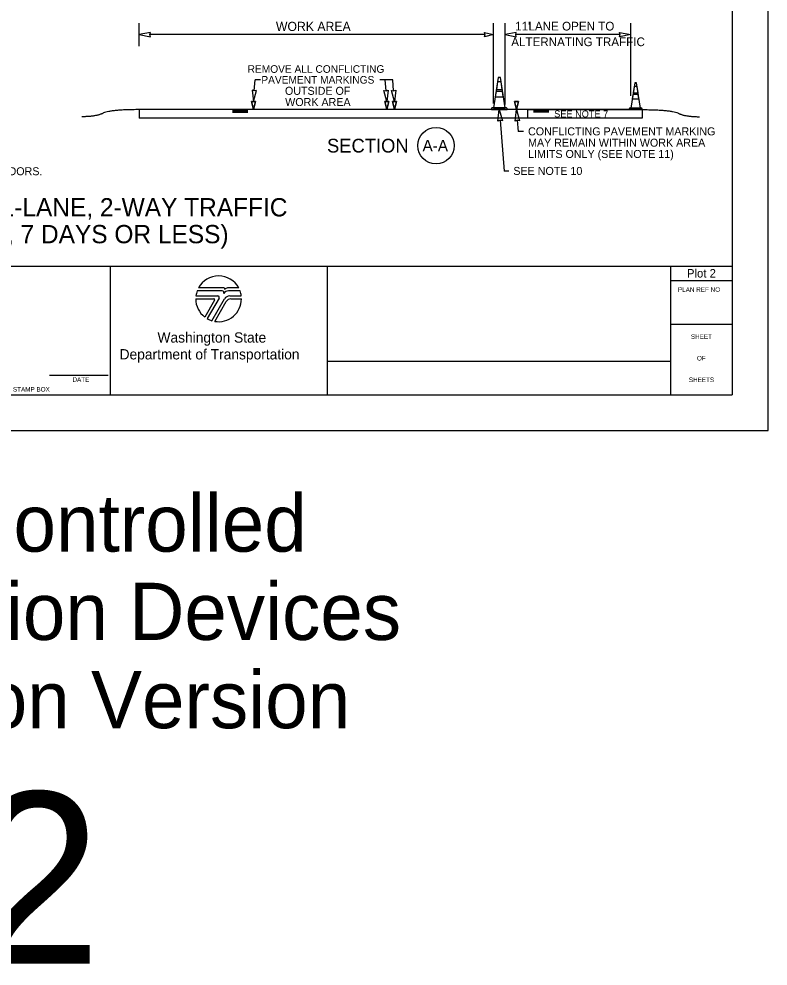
# Model space of a CAD drawing. Extents: x 99979.8 to 100075.7, y 99995 to 100010.7.
# Drawn here: x 100029.51 to 100036.06, y 99995.01 to 100003.29 of the extents above; entities that cross this region are included whole.
import ezdxf

# ---------------------------------------------------------------- set-up
doc = ezdxf.new("R2010")
doc.units = 0
for name, color, linetype in [('SH_DE_DetailHeading1Text', 7, 'Continuous'), ('SH_GI_GeneralNotesBodyText', 7, 'Continuous'), ('SH_GI_PlotLimits', 7, 'Continuous'), ('SH_GI_SheetBorder', 7, 'Continuous'), ('SH_GI_SheetLocationText', 7, 'Continuous'), ('SH_GI_SheetTextInCells', 7, 'Continuous'), ('SH_GI_WSDOTLogo', 7, 'Continuous'), ('TR_WZ_TrafficConeElev', 7, 'Continuous'), ('TR_WZ_WorkZoneDetails', 7, 'Continuous'), ('TR_WZ_WorkZoneTextCurrent', 7, 'Continuous')]:
    doc.layers.add(name, color=color, linetype=linetype)

msp = doc.modelspace()

# ---------------------------------------------------------------- linework, layer by layer
at = {"layer": 'SH_GI_PlotLimits'}
msp.add_lwpolyline([(100019.0625, 99999.6875), (100036.0625, 99999.6875), (100036.0625, 100010.6875), (100019.0625, 100010.6875)], close=True, dxfattribs=at)
at = {"layer": 'SH_GI_SheetBorder'}
for p, q in [((100035.75, 100010.375), (100035.75, 100000)), ((100020, 100001.1259), (100035.75, 100001.1259)), ((100030.3089, 100001.1259), (100030.3089, 100000)), ((100032.2055, 100001.1259), (100032.2055, 100000)), ((100035.2079, 100001.1259), (100035.2079, 100000)), ((100035.2079, 100001.0008), (100035.75, 100001.0008)), ((100035.2079, 100000.6176), (100035.75, 100000.6176)), ((100032.2055, 100000.2955), (100035.2079, 100000.2955)), ((100029.7797, 100000.1733), (100030.2914, 100000.1733)), ((100020, 100000), (100035.75, 100000))]:
    msp.add_line(p, q, dxfattribs=at)
at = {"layer": 'SH_GI_WSDOTLogo'}
for p, q in [((100031.2894, 100000.9094), (100031.0697, 100000.9094)), ((100031.303, 100000.9354), (100031.0815, 100000.9354)), ((100031.433, 100000.9354), (100031.3351, 100000.9354)), ((100031.343, 100000.9094), (100031.3429, 100000.9094)), ((100031.4448, 100000.9094), (100031.343, 100000.9094)), ((100031.0572, 100000.84), (100031.2148, 100000.84)), ((100031.059, 100000.8661), (100031.2496, 100000.8661)), ((100031.222, 100000.8277), (100031.1364, 100000.6807)), ((100031.261, 100000.8464), (100031.1567, 100000.6672)), ((100031.1989, 100000.6487), (100031.3089, 100000.839)), ((100031.2244, 100000.6428), (100031.3242, 100000.8156)), ((100031.3558, 100000.8661), (100031.4555, 100000.8661)), ((100031.3655, 100000.8394), (100031.4572, 100000.8394))]:
    msp.add_line(p, q, dxfattribs=at)
for centre, radius, start, end in [((100031.2572, 100000.84), 0.2, 28.47865, 151.53204), ((100031.2572, 100000.84), 0.2, 159.69598, 172.50569), ((100031.2894, 100000.8946), 0.0148, 327.8418, 89.99855), ((100031.3429, 100000.861), 0.0484, 89.99529, 147.82376), ((100031.303, 100000.9263), 0.00903, 329.87418, 90.00328), ((100031.3352, 100000.9066), 0.0287, 90.00721, 148.16763), ((100031.2572, 100000.84), 0.2, 7.49431, 20.29406), ((100031.2572, 100000.84), 0.2, 179.99864, 232.84327), ((100031.2149, 100000.8318), 0.0082, 329.74356, 90), ((100031.2572, 100000.84), 0.2, 260.54554, 359.80857), ((100031.2497, 100000.853), 0.0131, 329.76834, 90), ((100031.3558, 100000.8119), 0.0542, 90, 149.99738), ((100031.3654, 100000.7918), 0.0476, 90, 150.05432), ((100031.2572, 100000.84), 0.2, 239.79292, 253.0448)]:
    msp.add_arc(centre, radius, start, end, dxfattribs=at)
at = {"layer": 'TR_WZ_TrafficConeElev'}
for p, q in [((100033.697, 100002.7369), (100033.6871, 100002.6719)), ((100033.7273, 100002.7369), (100033.697, 100002.7369)), ((100033.7372, 100002.6719), (100033.7273, 100002.7369)), ((100033.684, 100002.6519), (100033.6771, 100002.6069)), ((100033.7403, 100002.6519), (100033.684, 100002.6519)), ((100033.6871, 100002.6719), (100033.7372, 100002.6719)), ((100033.7472, 100002.6069), (100033.7403, 100002.6519)), ((100034.8809, 100002.6256), (100034.8751, 100002.5881)), ((100034.9278, 100002.6256), (100034.8809, 100002.6256)), ((100034.8917, 100002.6965), (100034.8834, 100002.6423)), ((100034.8834, 100002.6423), (100034.9252, 100002.6423)), ((100034.9169, 100002.6965), (100034.8917, 100002.6965)), ((100034.9252, 100002.6423), (100034.9169, 100002.6965)), ((100034.9335, 100002.5881), (100034.9278, 100002.6256)), ((100033.6771, 100002.6069), (100033.7472, 100002.6069)), ((100034.8751, 100002.5881), (100034.9335, 100002.5881)), ((100033.6478, 100002.5094), (100033.6428, 100002.5044)), ((100033.6428, 100002.5044), (100033.6428, 100002.4944)), ((100033.6428, 100002.4944), (100033.7815, 100002.4944)), ((100033.6622, 100002.5094), (100033.6478, 100002.5094)), ((100033.7815, 100002.5044), (100033.7765, 100002.5094)), ((100033.7815, 100002.4944), (100033.7815, 100002.5044)), ((100034.8507, 100002.5069), (100034.8465, 100002.5027)), ((100034.8465, 100002.5027), (100034.8465, 100002.4944)), ((100034.8465, 100002.4944), (100034.9621, 100002.4944)), ((100034.8627, 100002.5069), (100034.8507, 100002.5069)), ((100034.9621, 100002.5027), (100034.958, 100002.5069)), ((100034.9621, 100002.4944), (100034.9621, 100002.5027))]:
    msp.add_line(p, q, dxfattribs=at)
for points in [[(100033.6622, 100002.5094), (100033.7622, 100002.5094), (100033.7215, 100002.7744), (100033.7028, 100002.7744)], [(100033.6622, 100002.5094), (100033.7622, 100002.5094), (100033.7215, 100002.7744), (100033.7028, 100002.7744)], [(100034.8627, 100002.5069), (100034.946, 100002.5069), (100034.9121, 100002.7277), (100034.8965, 100002.7277)], [(100034.8627, 100002.5069), (100034.946, 100002.5069), (100034.9121, 100002.7277), (100034.8965, 100002.7277)]]:
    msp.add_lwpolyline(points, close=True, dxfattribs=at)
for points in [[(100033.7765, 100002.5094), (100033.7622, 100002.5094), (100033.6622, 100002.5094)], [(100034.958, 100002.5069), (100034.946, 100002.5069), (100034.8627, 100002.5069)]]:
    msp.add_lwpolyline(points, dxfattribs=at)
at = {"layer": 'TR_WZ_WorkZoneDetails'}
for p, q in [((100030.5621, 100003.0504), (100030.5621, 100003.2504)), ((100033.6622, 100002.5494), (100033.6622, 100003.2504)), ((100033.7622, 100002.5394), (100033.7622, 100003.2504)), ((100034.8622, 100002.6142), (100034.8622, 100003.2504)), ((100033.5872, 100003.1504), (100030.6559, 100003.1504)), ((100034.7684, 100003.1504), (100033.8559, 100003.1504)), ((100031.5695, 100002.6576), (100031.5773, 100002.7552)), ((100031.6235, 100002.7552), (100031.5773, 100002.7552)), ((100032.7802, 100002.7552), (100032.6674, 100002.7552)), ((100032.7213, 100002.6576), (100032.7136, 100002.7552)), ((100032.788, 100002.6576), (100032.7802, 100002.7552)), ((100030.5621, 100002.4944), (100030.5621, 100002.4194)), ((100034.9621, 100002.4944), (100030.5621, 100002.4944)), ((100031.3791, 100002.4891), (100031.5121, 100002.4891)), ((100031.3791, 100002.4835), (100031.5121, 100002.4835)), ((100031.3791, 100002.4779), (100031.5121, 100002.4779)), ((100031.3791, 100002.4726), (100031.5121, 100002.4726)), ((100034.1451, 100002.4887), (100034.0121, 100002.4887)), ((100034.1451, 100002.4831), (100034.0121, 100002.4831)), ((100034.1451, 100002.4774), (100034.0121, 100002.4774)), ((100034.1451, 100002.4722), (100034.0121, 100002.4722)), ((100034.9621, 100002.4944), (100034.9621, 100002.4194)), ((100034.9621, 100002.4194), (100030.5621, 100002.4194)), ((100033.7196, 100002.4009), (100033.7549, 100001.9574)), ((100033.8696, 100002.4009), (100033.8774, 100002.3034)), ((100033.9235, 100002.3034), (100033.8774, 100002.3034)), ((100033.7949, 100001.9574), (100033.7549, 100001.9574))]:
    msp.add_line(p, q, dxfattribs=at)
for points in [[(100030.5621, 100003.1504), (100030.6604, 100003.1312), (100030.6559, 100003.1504), (100030.6604, 100003.1697)], [(100033.6622, 100003.1504), (100033.5835, 100003.1312), (100033.5872, 100003.1504), (100033.5835, 100003.1697)], [(100033.7622, 100003.1504), (100033.8604, 100003.1312), (100033.8559, 100003.1504), (100033.8604, 100003.1697)], [(100034.8622, 100003.1504), (100034.7639, 100003.1312), (100034.7684, 100003.1504), (100034.7639, 100003.1697)], [(100031.5621, 100002.5642), (100031.5891, 100002.6606), (100031.5695, 100002.6576), (100031.5506, 100002.6637)], [(100032.7288, 100002.5642), (100032.7018, 100002.6606), (100032.7214, 100002.6576), (100032.7402, 100002.6637)], [(100032.7954, 100002.5642), (100032.7685, 100002.6606), (100032.7881, 100002.6576), (100032.8069, 100002.6637)], [(100031.5621, 100002.4944), (100031.5454, 100002.5642), (100031.5788, 100002.5642)], [(100032.7288, 100002.4944), (100032.7121, 100002.5642), (100032.7454, 100002.5642)], [(100032.7955, 100002.4944), (100032.7788, 100002.5642), (100032.8121, 100002.5642)], [(100033.8622, 100002.4944), (100033.8455, 100002.5642), (100033.8788, 100002.5642)], [(100033.7122, 100002.4944), (100033.7391, 100002.3979), (100033.7195, 100002.4009), (100033.7007, 100002.3949)], [(100033.8622, 100002.4944), (100033.8891, 100002.3979), (100033.8695, 100002.4009), (100033.8507, 100002.3949)], [(100033.9621, 100002.4944), (100034.9621, 100002.4944), (100034.9621, 100002.4194), (100033.9621, 100002.4194)], [(100033.9621, 100002.4944), (100034.9621, 100002.4944), (100034.9621, 100002.4194), (100033.9621, 100002.4194)]]:
    msp.add_lwpolyline(points, close=True, dxfattribs=at)
for points in [[(100031.5788, 100002.5642), (100031.5454, 100002.5642), (100031.5621, 100002.4944), (100031.5788, 100002.5642)], [(100032.7454, 100002.5642), (100032.7121, 100002.5642), (100032.7288, 100002.4944), (100032.7454, 100002.5642)], [(100032.8121, 100002.5642), (100032.7788, 100002.5642), (100032.7955, 100002.4944), (100032.8121, 100002.5642)], [(100033.8788, 100002.5642), (100033.8455, 100002.5642), (100033.8622, 100002.4944), (100033.8788, 100002.5642)]]:
    msp.add_lwpolyline(points, dxfattribs=at)
msp.add_circle((100033.1587, 100002.1794), 0.16, dxfattribs=at)
for points in [[(100030.5621, 100002.4944), (100030.311, 100002.4944), (100030.1855, 100002.4322), (100030.06, 100002.4322)], [(100034.9621, 100002.4944), (100035.2133, 100002.4945), (100035.3388, 100002.4324), (100035.4643, 100002.4325)]]:
    msp.add_open_spline(points, degree=2, dxfattribs=at)

# ---------------------------------------------------------------- texts
at = {"layer": 'SH_DE_DetailHeading1Text'}
for s, p in [('SIMPLE TEMPORARY SIGNAL-CONTROLLED ALTERNATING 1-LANE, 2-WAY TRAFFIC', (100023.1573, 100001.5606)), ('25 WZSL + CHANNELIZING DEVICES (45+ MPH HIGHWAYS, 7 DAYS OR LESS)', (100023.4264, 100001.3259))]:
    msp.add_text(s, height=0.16, rotation=360, dxfattribs=at).set_placement(p)
at = {"layer": 'SH_GI_GeneralNotesBodyText'}
msp.add_text('ROADWAY WIDTH RESTRICTIONS. 30 DAY NOTICE REQUIRED ON MAJOR FREIGHT CORRIDORS.', height=0.07, rotation=360, dxfattribs=at).set_placement((100025.3222, 100001.9206))
at = {"layer": 'SH_GI_SheetBorder'}
msp.add_text('PLAN REF NO', height=0.040032, dxfattribs=at).set_placement((100035.2747, 100000.9008))
at = {"layer": 'SH_GI_SheetLocationText'}
for s, height, p in [('Plot 2', 0.07425, (100035.3528, 100001.0262)), (' Temp Signal-Controlled', 0.5, (100024.8187, 99998.6291)), ('Alt Traffic w/ Channelization Devices', 0.5, (100022.0024, 99997.8571)), ('(45+ mph) Short-Duration Version', 0.5, (100022.356, 99997.0851)), ('Plot 2', 1.5, (100025.1024, 99995.0267))]:
    msp.add_text(s, height=height, dxfattribs=at).set_placement(p)
at = {"layer": 'SH_GI_SheetTextInCells'}
for s, height, p in [('Washington State', 0.090072, (100030.7229, 100000.4571)), ('SHEET', 0.04003, (100035.3877, 100000.4896)), ('Department of Transportation', 0.090072, (100030.3916, 100000.3101)), ('OF', 0.04003, (100035.4406, 100000.3008)), ('DATE', 0.04003, (100029.9794, 100000.1141)), ('SHEETS', 0.04003, (100035.3698, 100000.112)), ('P.E. STAMP BOX', 0.040032, (100029.339, 100000.0286))]:
    msp.add_text(s, height=height, dxfattribs=at).set_placement(p)
at = {"layer": 'TR_WZ_WorkZoneDetails'}
for s, height, p in [('WORK AREA', 0.08, (100031.7586, 100003.1824)), ("11'", 0.076, (100033.851, 100003.1864)), (' LANE OPEN TO', 0.076, (100033.939, 100003.1864)), ('ALTERNATING TRAFFIC', 0.076, (100033.8165, 100003.0496))]:
    msp.add_text(s, height=height, dxfattribs=at).set_placement(p)
for s, height, p in [('SECTION', 0.12, (100032.2056, 100002.1194)), ('A-A', 0.1, (100033.0408, 100002.1294))]:
    msp.add_text(s, height=height, rotation=360, dxfattribs=at).set_placement(p)
at = {"layer": 'TR_WZ_WorkZoneTextCurrent'}
for s, height, p in [('REMOVE ALL CONFLICTING', 0.0665, (100031.5112, 100002.8164)), ('PAVEMENT MARKINGS', 0.0665, (100031.6311, 100002.7219)), ('OUTSIDE OF', 0.07, (100031.8376, 100002.6239)), ('WORK AREA', 0.07, (100031.8396, 100002.5259)), ('SEE NOTE 7', 0.06, (100034.1921, 100002.4269)), ('CONFLICTING PAVEMENT MARKING', 0.07, (100033.9635, 100002.2694)), ('MAY REMAIN WITHIN WORK AREA', 0.07, (100033.9635, 100002.1706)), ('LIMITS ONLY (SEE NOTE 11)', 0.07, (100033.9635, 100002.0718)), ('SEE NOTE 10', 0.07, (100033.8349, 100001.9234))]:
    msp.add_text(s, height=height, dxfattribs=at).set_placement(p)

doc.saveas('drawing.dxf')
